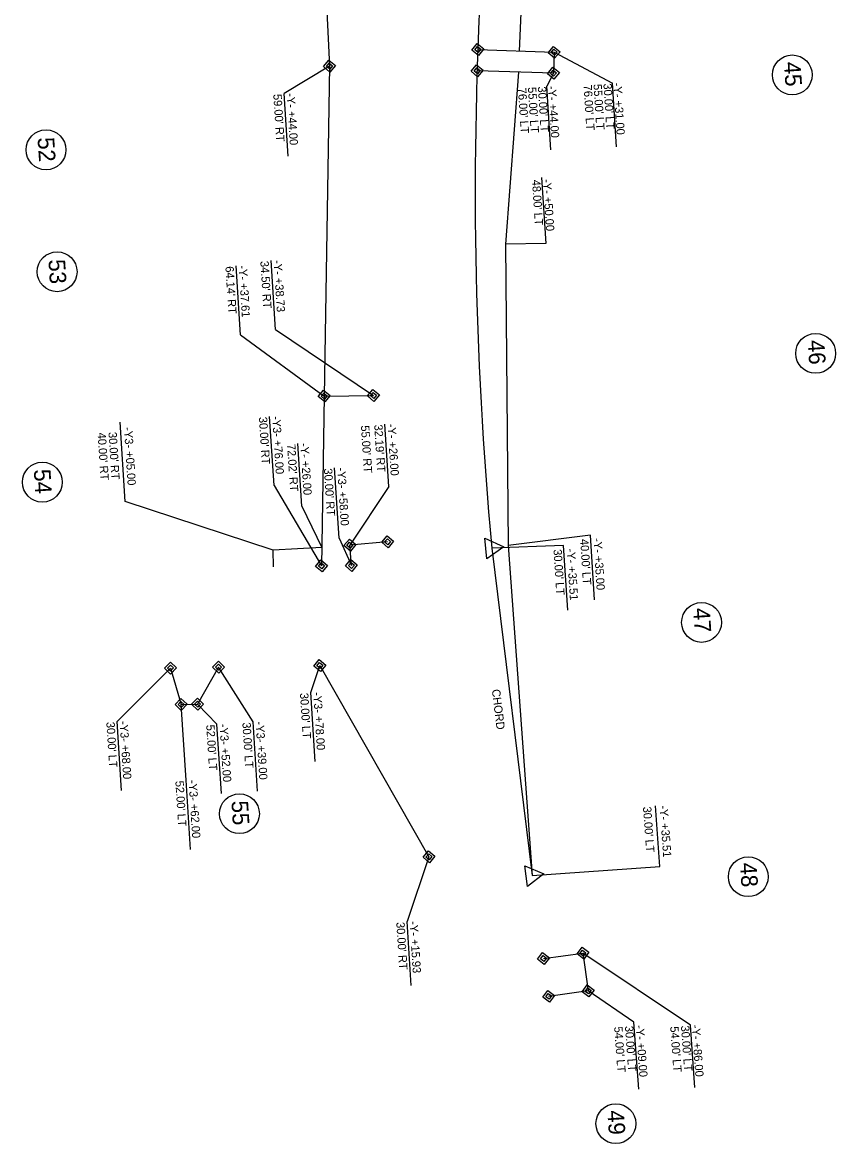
# Model space of a CAD drawing. Extents: x 1779796 to 1783527, y 810952 to 815815.
# Drawn here: x 1780736 to 1781226, y 810952 to 811628 of the extents above; entities that cross this region are included whole.
import ezdxf

# ---------------------------------------------------------------- set-up
doc = ezdxf.new("R2010")
doc.units = 0
for name, color, linetype in [('Prop Easement Aerial Utility', 7, 'Continuous'), ('Prop Easement Aerial Utility Station Offsets', 7, 'Continuous'), ('Prop Easement Construction', 7, 'Continuous'), ('Prop Easement Construction Station Offsets', 7, 'Continuous'), ('Prop Easement Permanent Drainage Utility', 7, 'Continuous'), ('Prop Easement Permanent Drainage Utility Station Offsets', 7, 'Continuous'), ('Prop Easement Permanent Utility', 7, 'Continuous'), ('Prop Easement Permanent Utility Station Offsets', 7, 'Continuous'), ('Prop Parcel Number CELL', 7, 'Continuous'), ('Prop Parcel Number Text', 7, 'Continuous'), ('Prop ROW Marker CELL', 7, 'Continuous'), ('Prop ROW Permanent Easement CELL', 7, 'Continuous'), ('Prop ROW RW Lines', 7, 'Continuous'), ('Prop ROW Station Offsets', 7, 'Continuous')]:
    doc.layers.add(name, color=color, linetype=linetype)

msp = doc.modelspace()

# ---------------------------------------------------------------- linework, layer by layer
at = {"layer": 'Prop Easement Aerial Utility'}
for p, q in [((1780917.85, 811402.69), (1780916.22, 811300.39)), ((1780915.22, 811240.36), (1780980.98, 811125.19))]:
    msp.add_line(p, q, dxfattribs=at)
at = {"layer": 'Prop Easement Aerial Utility Station Offsets'}
for p, q in [((1780887.61, 811348.79), (1780884.96, 811390.44)), ((1780909.73, 811224.18), (1780915.22, 811240.36)), ((1780912.38, 811182.53), (1780909.73, 811224.18)), ((1780980.98, 811125.19), (1780967.76, 811086.17)), ((1780970.21, 811047.62), (1780967.76, 811086.17))]:
    msp.add_line(p, q, dxfattribs=at)
msp.add_lwpolyline([(1780887.61, 811348.79), (1780916.22, 811300.39)], dxfattribs=at)
at = {"layer": 'Prop Easement Construction'}
for p, q in [((1781038.69, 811689.52), (1781035.38, 811610.48)), ((1781034.94, 811597.8), (1781027.03, 811494.21)), ((1781027.03, 811494.21), (1781028.77, 811312.59)), ((1780916.4, 811311.39), (1780887.06, 811309.9)), ((1780887.23, 811299.91), (1780887.06, 811309.9)), ((1781028.77, 811312.59), (1781043.08, 811113.94))]:
    msp.add_line(p, q, dxfattribs=at)
at = {"layer": 'Prop Easement Construction Station Offsets'}
for p, q in [((1781048.78, 811534.31), (1781051.31, 811494.53)), ((1781051.31, 811494.53), (1781027.03, 811494.21)), ((1780797.98, 811339.26), (1780794.95, 811387)), ((1780904.35, 811336.41), (1780901.96, 811374.11)), ((1780887.06, 811309.9), (1780797.98, 811339.26)), ((1781078.2, 811318.88), (1781028.77, 811312.59)), ((1781080.68, 811279.95), (1781078.2, 811318.88))]:
    msp.add_line(p, q, dxfattribs=at)
msp.add_lwpolyline([(1780904.35, 811336.41), (1780916.4, 811311.39)], dxfattribs=at)
at = {"layer": 'Prop Easement Permanent Drainage Utility'}
for p, q in [((1780956.07, 811314.95), (1780933.35, 811312.91)), ((1780934.22, 811300.69), (1780933.35, 811312.91)), ((1781049.95, 811063.92), (1781073.73, 811067.19)), ((1781073.73, 811067.19), (1781076.86, 811044.4)), ((1781076.86, 811044.4), (1781053.08, 811041.13))]:
    msp.add_line(p, q, dxfattribs=at)
at = {"layer": 'Prop Easement Permanent Drainage Utility Station Offsets'}
for p, q in [((1780956.85, 811348.11), (1780954.45, 811385.82)), ((1780926.83, 811317.04), (1780924.14, 811359.39)), ((1780956.85, 811348.11), (1780933.35, 811312.91)), ((1780926.83, 811317.04), (1780934.22, 811300.69)), ((1781107.34, 810985.33), (1781104.41, 811025.59)), ((1781141.23, 810986.14), (1781138.49, 811023.82))]:
    msp.add_line(p, q, dxfattribs=at)
for points in [[(1781138.49, 811023.82), (1781073.73, 811067.19)], [(1781104.41, 811025.59), (1781076.86, 811044.4)]]:
    msp.add_lwpolyline(points, dxfattribs=at)
at = {"layer": 'Prop Easement Permanent Utility'}
for p, q in [((1780911.62, 811802.39), (1780921, 811601.4)), ((1781010.4, 811611.41), (1781056.36, 811609.7)), ((1781056.36, 811609.7), (1781055.93, 811597.13)), ((1780921, 811601.4), (1780917.85, 811402.69)), ((1781055.93, 811597.13), (1781009.96, 811598.59)), ((1780917.85, 811402.69), (1780947.5, 811403.08)), ((1780854.23, 811239.35), (1780841.6, 811217.13)), ((1780825.24, 811238.86), (1780831.6, 811216.97)), ((1780831.6, 811216.97), (1780841.6, 811217.13))]:
    msp.add_line(p, q, dxfattribs=at)
at = {"layer": 'Prop Easement Permanent Utility Station Offsets'}
for p, q in [((1781056.36, 811609.7), (1781091.52, 811591.2)), ((1780921, 811601.4), (1780893.66, 811584.87)), ((1781055.93, 811597.13), (1781052.02, 811589.36)), ((1781093.97, 811552.71), (1781091.52, 811591.2)), ((1780896.06, 811547.16), (1780893.66, 811584.87)), ((1781054.46, 811550.88), (1781052.02, 811589.36)), ((1780888.49, 811442.71), (1780885.84, 811484.37)), ((1780867.43, 811439.49), (1780864.79, 811481.15)), ((1780888.49, 811442.71), (1780947.5, 811403.08)), ((1780867.43, 811439.49), (1780917.85, 811402.69)), ((1780795.72, 811165.11), (1780793.07, 811206.76)), ((1780877.68, 811164.79), (1780875.03, 811206.44)), ((1780855.89, 811163.37), (1780853.25, 811205.02)), ((1780837.29, 811129.59), (1780834.64, 811171.24))]:
    msp.add_line(p, q, dxfattribs=at)
for points in [[(1780875.03, 811206.44), (1780854.23, 811239.35)], [(1780793.07, 811206.76), (1780825.24, 811238.86)], [(1780834.64, 811171.24), (1780831.6, 811216.97)], [(1780853.25, 811205.02), (1780841.6, 811217.13)]]:
    msp.add_lwpolyline(points, dxfattribs=at)
at = {"layer": 'Prop Parcel Number CELL'}
for p, q in [((1781199.84, 811596.11), (1781199.84, 811596.11)), ((1780750.25, 811550.97), (1780750.25, 811550.97)), ((1780756.93, 811477.54), (1780756.93, 811477.54)), ((1781213.95, 811428.38), (1781213.95, 811428.38)), ((1780748.04, 811350.8), (1780748.04, 811350.8)), ((1781145.21, 811266.34), (1781145.21, 811266.34)), ((1780866.8, 811151.13), (1780866.8, 811151.13)), ((1781173.36, 811113.19), (1781173.36, 811113.19)), ((1781093.57, 810964.46), (1781093.57, 810964.46))]:
    msp.add_line(p, q, dxfattribs=at)
for centre in [(1781199.84, 811596.11), (1780750.25, 811550.97), (1780756.93, 811477.54), (1781213.95, 811428.38), (1780748.04, 811350.8), (1781145.21, 811266.34), (1780866.8, 811151.13), (1781173.36, 811113.19), (1781093.57, 810964.46)]:
    msp.add_circle(centre, 12, dxfattribs=at)
at = {"layer": 'Prop ROW Marker CELL'}
for p, q in [((1781010.4, 811611.41), (1781010.4, 811611.41)), ((1781056.36, 811609.7), (1781056.36, 811609.7)), ((1780921, 811601.4), (1780921, 811601.4)), ((1781009.96, 811598.59), (1781009.96, 811598.59)), ((1781055.93, 811597.13), (1781055.93, 811597.13)), ((1780917.85, 811402.69), (1780917.85, 811402.69)), ((1780947.5, 811403.08), (1780947.5, 811403.08)), ((1780956.07, 811314.95), (1780956.07, 811314.95)), ((1780933.35, 811312.91), (1780933.35, 811312.91)), ((1781018.86, 811311.15), (1781018.86, 811311.15)), ((1780916.22, 811300.39), (1780916.22, 811300.39)), ((1780934.22, 811300.69), (1780934.22, 811300.69)), ((1780854.23, 811239.35), (1780854.23, 811239.35)), ((1780915.22, 811240.36), (1780915.22, 811240.36)), ((1780825.24, 811238.86), (1780825.24, 811238.86)), ((1780831.6, 811216.97), (1780831.6, 811216.97)), ((1780841.6, 811217.13), (1780841.6, 811217.13)), ((1780980.98, 811125.19), (1780980.98, 811125.19)), ((1781043.08, 811113.94), (1781043.08, 811113.94)), ((1781049.95, 811063.92), (1781049.95, 811063.92)), ((1781073.73, 811067.19), (1781073.73, 811067.19)), ((1781076.86, 811044.4), (1781076.86, 811044.4)), ((1781053.08, 811041.13), (1781053.08, 811041.13))]:
    msp.add_line(p, q, dxfattribs=at)
for points in [[(1781014.69, 811317.03), (1781026.03, 811311.83), (1781015.87, 811304.59)], [(1781038.67, 811119.64), (1781050.22, 811114.92), (1781040.37, 811107.25)]]:
    msp.add_lwpolyline(points, close=True, dxfattribs=at)
at = {"layer": 'Prop ROW Permanent Easement CELL'}
for points in [[(1781013.98, 811611.73), (1781010.72, 811607.83), (1781006.81, 811611.09), (1781010.07, 811615)], [(1781012.19, 811611.57), (1781010.56, 811609.62), (1781008.6, 811611.25), (1781010.24, 811613.2)], [(1781059.95, 811610.02), (1781056.69, 811606.12), (1781052.78, 811609.38), (1781056.04, 811613.29)], [(1781058.16, 811609.86), (1781056.53, 811607.91), (1781054.57, 811609.54), (1781056.2, 811611.5)], [(1780924.59, 811601.72), (1780921.32, 811597.81), (1780917.41, 811601.07), (1780920.68, 811604.98)], [(1780922.79, 811601.56), (1780921.16, 811599.6), (1780919.21, 811601.24), (1780920.84, 811603.19)], [(1781013.54, 811598.91), (1781010.28, 811595), (1781006.37, 811598.26), (1781009.63, 811602.17)], [(1781011.75, 811598.75), (1781010.12, 811596.79), (1781008.16, 811598.43), (1781009.79, 811600.38)], [(1781059.52, 811597.46), (1781056.25, 811593.55), (1781052.35, 811596.81), (1781055.61, 811600.72)], [(1781057.73, 811597.3), (1781056.09, 811595.34), (1781054.14, 811596.97), (1781055.77, 811598.93)], [(1780921.43, 811403.01), (1780918.17, 811399.1), (1780914.26, 811402.37), (1780917.52, 811406.27)], [(1780919.64, 811402.85), (1780918.01, 811400.89), (1780916.05, 811402.53), (1780917.69, 811404.48)], [(1780951.09, 811403.4), (1780947.82, 811399.49), (1780943.92, 811402.76), (1780947.18, 811406.66)], [(1780949.3, 811403.24), (1780947.66, 811401.29), (1780945.71, 811402.92), (1780947.34, 811404.87)], [(1780936.93, 811313.23), (1780933.67, 811309.32), (1780929.76, 811312.59), (1780933.02, 811316.5)], [(1780935.14, 811313.07), (1780933.51, 811311.12), (1780931.55, 811312.75), (1780933.18, 811314.7)], [(1780959.65, 811315.27), (1780956.39, 811311.36), (1780952.48, 811314.63), (1780955.74, 811318.53)], [(1780957.86, 811315.11), (1780956.23, 811313.16), (1780954.27, 811314.79), (1780955.9, 811316.74)], [(1780919.81, 811300.71), (1780916.54, 811296.8), (1780912.64, 811300.07), (1780915.9, 811303.97)], [(1780918.02, 811300.55), (1780916.38, 811298.6), (1780914.43, 811300.23), (1780916.06, 811302.18)], [(1780937.81, 811301.01), (1780934.54, 811297.1), (1780930.64, 811300.37), (1780933.9, 811304.27)], [(1780936.01, 811300.85), (1780934.38, 811298.9), (1780932.43, 811300.53), (1780934.06, 811302.48)], [(1780828.83, 811238.92), (1780825.29, 811235.26), (1780821.64, 811238.8), (1780825.18, 811242.46)], [(1780827.03, 811238.89), (1780825.27, 811237.06), (1780823.44, 811238.83), (1780825.21, 811240.66)], [(1780857.83, 811239.41), (1780854.29, 811235.75), (1780850.63, 811239.29), (1780854.17, 811242.95)], [(1780856.03, 811239.38), (1780854.26, 811237.55), (1780852.43, 811239.32), (1780854.2, 811241.15)], [(1780918.81, 811240.69), (1780915.54, 811236.78), (1780911.64, 811240.04), (1780914.9, 811243.95)], [(1780917.02, 811240.52), (1780915.38, 811238.57), (1780913.43, 811240.2), (1780915.06, 811242.16)], [(1780835.2, 811217.03), (1780831.66, 811213.37), (1780828, 811216.91), (1780831.54, 811220.57)], [(1780845.2, 811217.19), (1780841.66, 811213.53), (1780838, 811217.07), (1780841.54, 811220.73)], [(1780843.4, 811217.16), (1780841.63, 811215.33), (1780839.8, 811217.1), (1780841.57, 811218.93)], [(1780833.4, 811217), (1780831.63, 811215.17), (1780829.8, 811216.94), (1780831.57, 811218.77)], [(1780984.56, 811125.51), (1780981.3, 811121.61), (1780977.39, 811124.87), (1780980.65, 811128.78)], [(1780982.77, 811125.35), (1780981.14, 811123.4), (1780979.18, 811125.03), (1780980.81, 811126.98)], [(1781077.29, 811067.67), (1781074.22, 811063.62), (1781070.16, 811066.7), (1781073.24, 811070.75)], [(1781053.52, 811064.41), (1781050.44, 811060.35), (1781046.39, 811063.43), (1781049.46, 811067.49)], [(1781051.73, 811064.17), (1781050.2, 811062.14), (1781048.17, 811063.68), (1781049.71, 811065.7)], [(1781075.51, 811067.43), (1781073.97, 811065.4), (1781071.95, 811066.94), (1781073.48, 811068.97)], [(1781056.65, 811041.62), (1781053.57, 811037.57), (1781049.51, 811040.64), (1781052.59, 811044.7)], [(1781080.42, 811044.89), (1781077.35, 811040.83), (1781073.29, 811043.91), (1781076.37, 811047.97)], [(1781078.64, 811044.64), (1781077.1, 811042.62), (1781075.07, 811044.15), (1781076.61, 811046.18)], [(1781054.86, 811041.38), (1781053.33, 811039.35), (1781051.3, 811040.89), (1781052.84, 811042.92)]]:
    msp.add_lwpolyline(points, close=True, dxfattribs=at)
at = {"layer": 'Prop ROW RW Lines'}
msp.add_line((1781018.86, 811311.15), (1781043.08, 811113.94), dxfattribs=at)
msp.add_arc((1783308.81, 811525.98), 2300, 167.88753, 185.35942, dxfattribs=at)
at = {"layer": 'Prop ROW Station Offsets'}
for p, q in [((1781064.59, 811273.73), (1781062.12, 811312.66)), ((1781120.01, 811119.35), (1781117.36, 811155.79)), ((1781043.08, 811113.94), (1781120.01, 811119.35))]:
    msp.add_line(p, q, dxfattribs=at)
msp.add_lwpolyline([(1781062.12, 811312.66), (1781018.86, 811311.15)], dxfattribs=at)

# ---------------------------------------------------------------- texts
at = {"layer": 'Prop Easement Aerial Utility Station Offsets'}
for s, p in [("30.00' RT", (1780878.48, 811390.01)), ('-Y3- +76.00', (1780886.46, 811390.52)), ("30.00' LT", (1780903.24, 811223.75)), ('-Y3- +78.00', (1780911.23, 811224.26)), ("30.00' RT", (1780961.27, 811085.74)), ('-Y- +15.93', (1780969.26, 811086.25))]:
    msp.add_text(s, height=5, rotation=273.6363, dxfattribs=at).set_placement(p)
at = {"layer": 'Prop Easement Construction Station Offsets'}
for s, rotation, p in [("48.00' LT", 273.63495, (1781043.04, 811532.81)), ('-Y- +50.00', 273.63495, (1781049.58, 811533.23)), ('-Y3- +05.00', 273.63495, (1780797.23, 811383.77)), ("40.00' RT", 273.63495, (1780781.32, 811380.48)), ("30.00' RT", 273.63495, (1780787.86, 811380.89)), ("72.02' RT", 273.6363, (1780895.47, 811373.68)), ('-Y- +26.00', 273.6363, (1780903.45, 811374.19)), ("40.00' LT", 273.6363, (1781072.05, 811316.47)), ('-Y- +35.00', 273.6363, (1781080.03, 811316.98))]:
    msp.add_text(s, height=5, rotation=rotation, dxfattribs=at).set_placement(p)
at = {"layer": 'Prop Easement Permanent Drainage Utility Station Offsets'}
for s, rotation, p in [("55.00' RT", 273.6363, (1780939.98, 811384.88)), ("32.19' RT", 273.6363, (1780947.97, 811385.39)), ('-Y- +26.00', 273.6363, (1780955.95, 811385.89)), ("30.00' RT", 273.6363, (1780917.66, 811358.96)), ('-Y3- +58.00', 273.6363, (1780925.64, 811359.46)), ("30.00' LT", 274.15877, (1781099.01, 811023.24)), ('-Y- +09.00', 274.15877, (1781105.49, 811023.71)), ("30.00' LT", 274.15877, (1781132.76, 811023.39)), ('-Y- +86.00', 274.15877, (1781139.24, 811023.86)), ("54.00' LT", 274.15877, (1781092.53, 811022.77)), ("54.00' LT", 274.15877, (1781126.28, 811022.92))]:
    msp.add_text(s, height=5, rotation=rotation, dxfattribs=at).set_placement(p)
at = {"layer": 'Prop Easement Permanent Utility Station Offsets'}
for s, p in [("55.00' LT", (1781080.06, 811590.45)), ("30.00' LT", (1781086.05, 811590.83)), ('-Y- +31.00', (1781092.04, 811591.21)), ("59.00' RT", (1780887.18, 811584.44)), ('-Y- +44.00', (1780895.16, 811584.95)), ("76.00' LT", (1781034.57, 811588.23)), ("55.00' LT", (1781040.56, 811588.61)), ("30.00' LT", (1781046.55, 811588.99)), ('-Y- +44.00', (1781052.54, 811589.37)), ("76.00' LT", (1781074.08, 811590.07)), ("34.50' RT", (1780879.36, 811483.93)), ('-Y- +38.73', (1780887.34, 811484.44)), ("64.14' RT", (1780858.3, 811480.71)), ('-Y- +37.61', (1780866.29, 811481.22)), ("30.00' LT", (1780786.58, 811206.33)), ('-Y3- +68.00', (1780794.57, 811206.84)), ("30.00' LT", (1780868.54, 811206.01)), ('-Y3- +39.00', (1780876.53, 811206.51)), ("52.00' LT", (1780846.76, 811204.59)), ('-Y3- +52.00', (1780854.74, 811205.09)), ("52.00' LT", (1780828.16, 811170.81)), ('-Y3- +62.00', (1780836.14, 811171.32))]:
    msp.add_text(s, height=5, rotation=273.6363, dxfattribs=at).set_placement(p)
at = {"layer": 'Prop Parcel Number Text'}
for s, p in [('45', (1781194.83, 811603.72)), ('52', (1780745.16, 811558.27)), ('53', (1780751.7, 811484.75)), ('46', (1781209.14, 811436.2)), ('54', (1780742.89, 811358.35)), ('47', (1781140.15, 811274.83)), ('55', (1780861.94, 811158.74)), ('48', (1781168.34, 811121.44)), ('49', (1781088.42, 810972.28))]:
    msp.add_text(s, height=10, rotation=273.6363, dxfattribs=at).set_placement(p)
at = {"layer": 'Prop ROW Station Offsets'}
for s, rotation, p in [("30.00' LT", 273.6363, (1781055.97, 811310.25)), ('-Y- +35.51', 273.6363, (1781063.95, 811310.76)), ('CHORD', 277.00145, (1781018.82, 811225.82)), ("30.00' LT", 274.15877, (1781109.88, 811155.24)), ('-Y- +35.51', 274.15877, (1781119.85, 811155.97))]:
    msp.add_text(s, height=5, rotation=rotation, dxfattribs=at).set_placement(p)

doc.saveas('drawing.dxf')
